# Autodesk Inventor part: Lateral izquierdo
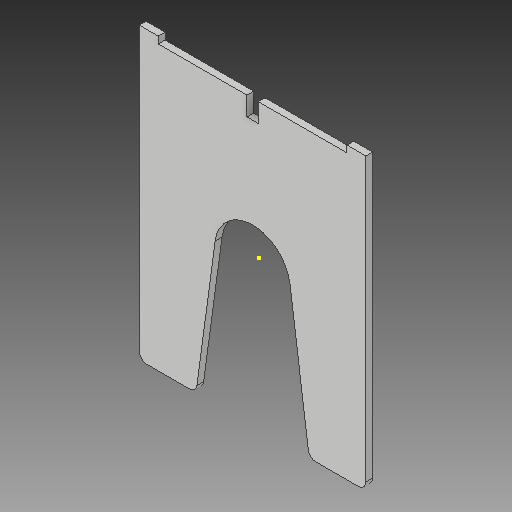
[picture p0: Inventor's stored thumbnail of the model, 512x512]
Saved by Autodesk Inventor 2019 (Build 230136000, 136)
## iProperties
Created: 2019-02
Part Number: Lateral izquierdo
Material: Genérico
Document SubType Name: Modeling
Designer: Juan Manuel Montalvo Navarrete
Density: 1 g/cm^3
Appearance: Valor por defecto
Author: Juan Manuel Montalvo Navarrete
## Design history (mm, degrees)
sketch "Boceto1"
  geometry: 1 further point
sketch "Boceto2"
  geometry: L1 (300, 375)-(300, -355); L2 (-300, -355)-(-300, 375); L3 (-300, 375)-(300, -375); L4 (300, 375)-(-300, -375); L5 (-280, -375)-(-167.459, -375); L6 (280, -375)-(167.459, -375); L7 (-147.642, -357.701)-(-99.084, -1.493); L8 (99.084, -1.493)-(147.642, -357.701); L9 (-300, 375)-(-300, 393); L10 (-300, 393)-(-250, 393); L11 (-250, 393)-(-250, 375); L12 (300, 375)-(300, 393); L13 (300, 393)-(250, 393); L14 (250, 393)-(250, 375); L15 (-15, 375)-(-15, 325); L16 (-15, 325)-(15, 325); L17 (15, 325)-(15, 375); L18 (-250, 375)-(-15, 375); L19 (15, 375)-(250, 375); A1 r 100 centre (0, -15) between (99.084, -1.493) and (-99.084, -1.493); A2 r 20 centre (-167.459, -355) between (-167.459, -375) and (-147.642, -357.701); A3 r 20 centre (-280, -355) between (-300, -355) and (-280, -375); A4 r 20 centre (167.459, -355) between (147.642, -357.701) and (167.459, -375); A5 r 20 centre (280, -355) between (280, -375) and (300, -355); 4 further points
  constraints: 38 end point, 11 perpendicular, 10 point on circle, 10 point on line, 10 tangent, 5 centre point, 4 horizontal, 3 equal radius, 3 vertical, 2 collinear, 2 midpoint, 1 parallel
  dimensions: "d1" = 150 distance of L4.end point (-150, -375); "d2" = 600 distance of L2.end L1.start; "d3" = 150 distance of L3.end point (150, -375); "d4" = 300 distance from line of L2 point (0, 725.354); "d5" = 100 radius of A1; "d6" = 360 vertical distance of L4.end A1.centre; "d7" = 20 radius of A2; "d8" = 18 distance of L2.end L9.end; "d9" = 50 distance of L9.end L10.end; "d10" = 18 distance of L1.start L12.end; "d11" = 50 distance of L12.end L13.end; "d13" = 18 distance of L10.end L11.end; "d16" = 50 distance of L15.start L15.end; "d17" = 30 distance of L15.end L16.end; "d18" = 285 distance between parallel lines of L2 L15
extrude "Extrusión1" new body sketch "Boceto2" distance "d14" = 18; taper "d15" = 0 deg
node "Sólido1"
